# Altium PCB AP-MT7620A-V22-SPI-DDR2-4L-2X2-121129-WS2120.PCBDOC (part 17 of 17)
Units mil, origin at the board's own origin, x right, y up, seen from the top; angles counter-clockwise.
Board outline 7316 x 4279 mil, 4 copper layers (Top, Inner Layer 2, Inner Layer 3, Bottom), stack 35.4 mil thick; 640 components, 473 nets, 2041 pads, 2358 vias.
Unrouted connection lines stored in the file: 11.
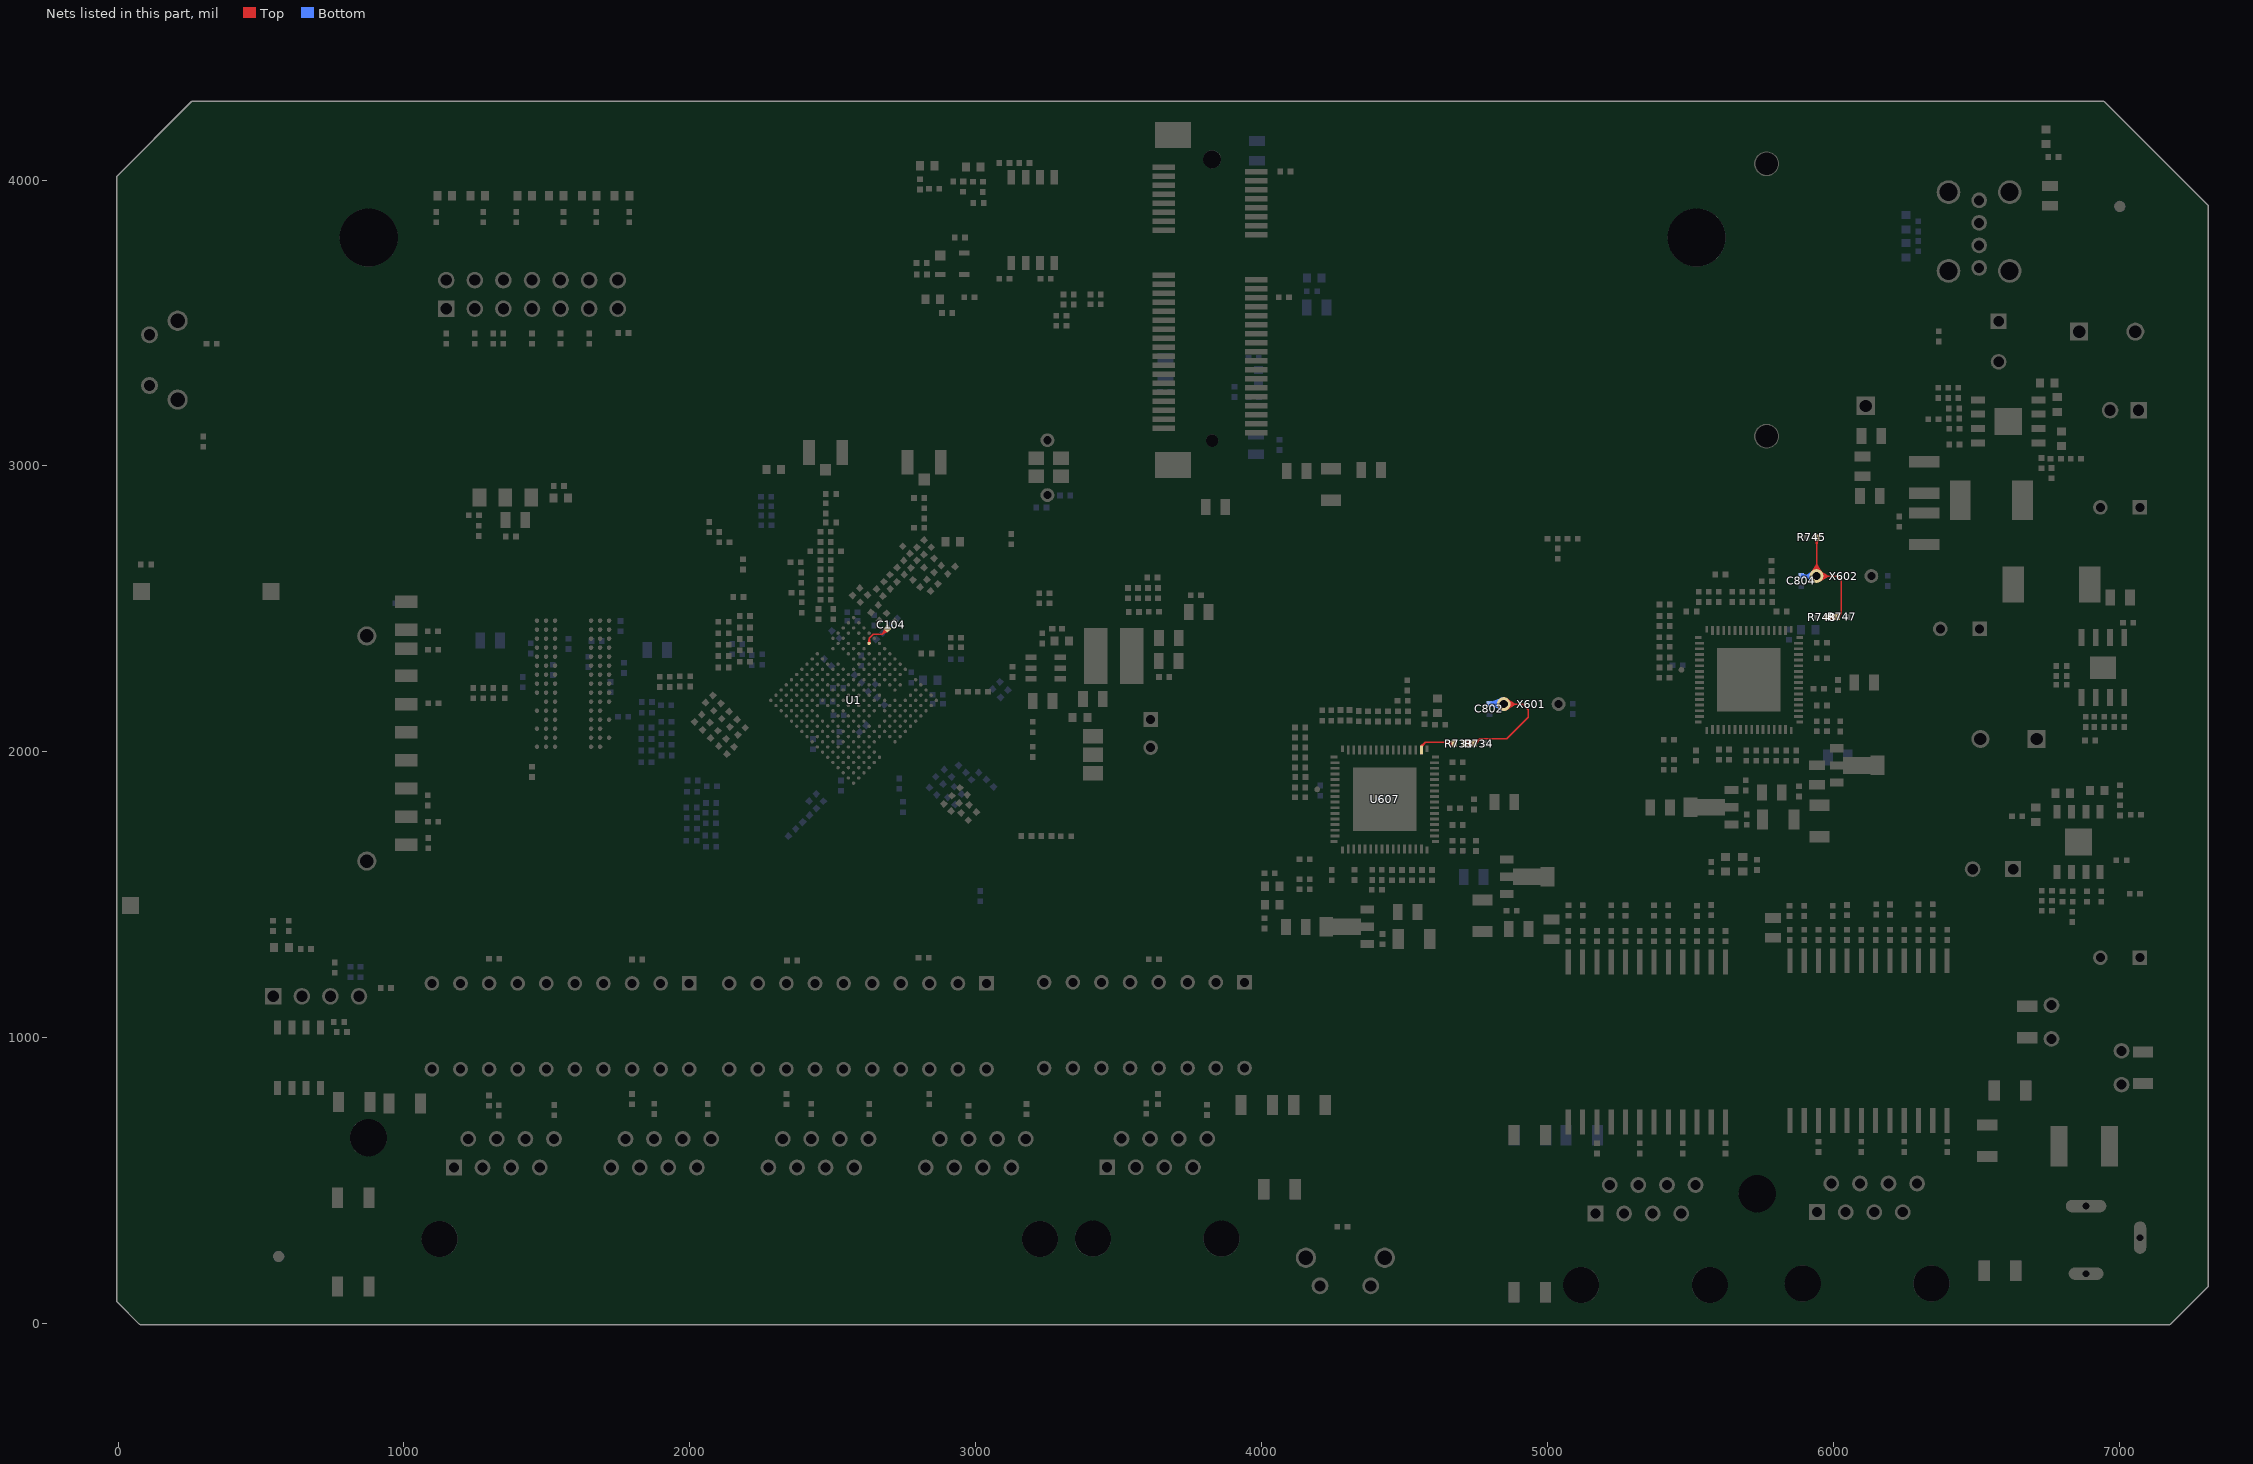
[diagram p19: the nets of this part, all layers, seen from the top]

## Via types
v1: diameter 20, hole 12, Top to Bottom, 2117 vias
v2: diameter 16, hole 8, Top to Bottom, 241 vias

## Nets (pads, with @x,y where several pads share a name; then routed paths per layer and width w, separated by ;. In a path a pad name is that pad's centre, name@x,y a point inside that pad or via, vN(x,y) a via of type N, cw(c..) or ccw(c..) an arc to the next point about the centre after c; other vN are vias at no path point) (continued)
X2_IP1001-21_1-CPU-RT0: C804.1 R745.1 R747.1 R748.1 X602.2 | length 2038.9
  Top w5: X602.2@5920.23,2621.62 5942,2654.28 ; X602.2@5924.7,2619.05 5942,2654.28 ; X602.2@5929.4,2617.11 5942,2654.28 ; X602.2@5934.26,2615.81 5942,2654.28 ; R745.1@5934.58,2748.88 5942,2725 ; X602.2@5941.5,2608.36 5980.14,2615.05 ; X602.2@5941.5,2621.74 5980.14,2615.05 ; X602.2@5942.68,2603.47 5980.14,2615.05 ; X602.2@5942.68,2626.63 5980.14,2615.05 ; X602.2@5944.49,2598.72 5980.14,2615.05 ; X602.2@5944.49,2631.38 5980.14,2615.05 ; X602.2@5946.94,2594.19 5980.14,2615.05 ; X602.2@5946.94,2635.91 5980.14,2615.05 ; X602.2@5947.63,2615.44 5942,2654.28 ; R745.1@5949.42,2748.88 5942,2725 ; X602.2@5952.55,2616.48 5942,2654.28 ; X602.2@5957.35,2618.16 5942,2654.28 ; X602.2@5961.95,2620.48 5942,2654.28 ; R748.1@5979.01,2470.95 6012.95,2470.95 R747.1@6014,2472 ; R748.1@5980.14,2463.53 6004.01,2470.95 R748.1@5980.14,2478.37 ; R747.1@6009.8,2478.21 6028,2486 ; R747.1@6011.29,2478.99 R748.1@5988.3,2466.07 ; R747.1@6011.83,2464.82 R748.1@5986.89,2476.27 ; R747.1@6012.57,2479.36 R748.1@5988.97,2470.95 ; R747.1@6013.19,2464.54 R748.1@5988.97,2470.95 ; R747.1@6014.14,2479.5 R748.1@5986.89,2476.27 ; R747.1@6014.63,2464.53 R748.1@5988.3,2466.07 ; R747.1@6020.21,2467.8 6028,2486 ; X602.2@5940.93,2615.05 6012.95,2615.05 6028,2600 6028,2486 ; X602.2@5940.93,2615.05 5942,2616.12 R745.1@5942,2750 5942,2725 ; X602.2@5940.93,2615.05 5942,2654.28 ; R748.1@5986.89,2476.27 R747.1@6014,2472 ; R748.1@5988.3,2466.07 R747.1@6014,2472 ; R748.1@5988.97,2470.95 R747.1@6014,2472 ; R747.1@6014,2472 6021.25,2472 6021.25,2479.25 6028,2486 ; R747.1@6014,2472 6028,2486
  Bottom w4.5: C804.1@5888.09,2612.75 5911.53,2615.05 ; C804.1@5888.35,2619.23 5911.53,2615.05 ; C804.1@5888.97,2608.31 5911.53,2615.05 ; C804.1@5889.58,2623.59 5911.53,2615.05 ; X602.2@5934.53,2594.04 5903.21,2615.05 ; X602.2@5934.53,2636.06 5903.21,2615.05 ; X602.2@5936.88,2598.06 5903.21,2615.05 ; X602.2@5936.88,2632.04 5903.21,2615.05 ; X602.2@5938.7,2602.28 5903.21,2615.05 ; X602.2@5938.7,2627.82 5903.21,2615.05 ; X602.2@5939.98,2606.64 5903.21,2615.05 ; X602.2@5939.98,2623.46 5903.21,2615.05 ; X602.2@5940.72,2611.09 5903.21,2615.05 ; X602.2@5940.72,2619.01 5903.21,2615.05 ; X602.2@5940.93,2615.05 5888.05,2615.05 5888,2615 C804.1@5888,2616 5911.53,2615.05
X2_IP1001-O_1-CPU-RT0: C802.1 R733.2 R734.1 X601.2 | length 2750.7
  Top w4.5: R734.1@4744,2029 R734.1@4745,2029
  Top w5: R733.2@4709.58,2021.51 R734.1@4735.68,2023.82 ; R733.2@4709.58,2036.49 R734.1@4735.68,2034.18 ; R733.2@4712.52,2021.94 R734.1@4735.68,2034.18 ; R733.2@4712.52,2036.06 R734.1@4735.68,2023.82 ; R734.1@4739.7,2035.15 4762.5,2046.5 ; R734.1@4742.88,2021.58 R733.2@4719,2029 ; R734.1@4742.88,2036.42 R733.2@4719,2029 ; R734.1@4749.9,2024.37 4762.5,2046.5 ; X601.2@4846.93,2167.05 4912.99,2167.05 4932,2148.04 4932,2121 4857.5,2046.5 4762.5,2046.5 ; X601.2@4847.5,2160.36 4886.14,2167.05 ; X601.2@4847.5,2173.74 4886.14,2167.05 ; X601.2@4848.68,2155.47 4886.14,2167.05 ; X601.2@4848.68,2178.63 4886.14,2167.05 ; X601.2@4850.49,2150.72 4886.14,2167.05 ; X601.2@4850.49,2183.38 4886.14,2167.05 ; X601.2@4852.94,2146.19 4886.14,2167.05 ; X601.2@4852.94,2187.91 4886.14,2167.05 ; R733.2@4710,2029 4745,2029 4762.5,2046.5 ; R733.2@4710,2029 R734.1@4735.68,2034.18 ; R733.2@4710,2029 R734.1@4735,2029 ; R733.2@4710,2029 R734.1@4735.68,2023.82 ; R733.2@4719,2029 R734.1@4744,2029 4762.5,2046.5 ; R734.1@4735,2029 4711.12,2036.42 R734.1@4735,2029 ; R734.1@4735,2029 4711.12,2021.58 R734.1@4735,2029
  Bottom w5: C802.1@4797.83,2160.55 4822.03,2167 ; C802.1@4798.42,2175.36 4822.03,2167 ; X601.2@4838.49,2147.05 C802.1@4803.88,2173.43 ; X601.2@4839.12,2187.31 C802.1@4804.42,2162.3 ; X601.2@4840.84,2146.21 C802.1@4806.19,2167.63 ; X601.2@4840.89,2187.91 4807.71,2167 ; X601.2@4840.94,2146.18 4807.71,2167 ; X601.2@4841.35,2151.3 C802.1@4803.88,2173.43 ; X601.2@4841.44,2188.06 C802.1@4806.19,2167.63 ; X601.2@4841.86,2182.98 C802.1@4804.42,2162.3 ; X601.2@4843.27,2150.74 C802.1@4806.19,2167.63 ; X601.2@4843.34,2183.37 4807.71,2167 ; X601.2@4843.39,2150.72 4807.71,2167 ; X601.2@4843.67,2155.8 C802.1@4803.88,2173.43 ; X601.2@4843.73,2183.45 C802.1@4806.19,2167.63 ; X601.2@4843.78,2145.57 C802.1@4804.42,2162.3 ; X601.2@4844.05,2178.4 C802.1@4804.42,2162.3 ; X601.2@4844.65,2188.64 C802.1@4803.88,2173.43 ; X601.2@4845.08,2155.48 C802.1@4806.19,2167.63 ; X601.2@4845.16,2178.63 4807.71,2167 ; X601.2@4845.19,2155.47 4807.71,2167 ; X601.2@4845.41,2178.66 C802.1@4806.19,2167.63 ; X601.2@4845.43,2160.51 C802.1@4803.88,2173.43 ; X601.2@4845.5,2150.4 C802.1@4804.42,2162.3 ; X601.2@4845.66,2173.64 C802.1@4804.42,2162.3 ; X601.2@4846.16,2183.74 C802.1@4803.88,2173.43 ; X601.2@4846.28,2160.37 C802.1@4806.19,2167.63 ; X601.2@4846.36,2160.36 4807.71,2167 ; X601.2@4846.34,2173.74 4807.71,2167 ; X601.2@4846.47,2173.75 C802.1@4806.19,2167.63 ; X601.2@4846.62,2155.34 C802.1@4804.42,2162.3 ; X601.2@4847.07,2178.76 C802.1@4803.88,2173.43 ; X601.2@4847.15,2160.34 C802.1@4804.42,2162.3 ; X601.2@4847.4,2173.75 C802.1@4803.88,2173.43 ; C802.1@4803.88,2173.43 X601.2@4846.93,2167.05 ; C802.1@4804.42,2162.3 X601.2@4846.93,2167.05 ; C802.1@4806.19,2167.63 X601.2@4846.93,2167.05 ; 4807.71,2167 X601.2@4846.93,2167.05 ; 4822.03,2167 C802.1@4797,2168 4797,2167 X601.2@4846.93,2167.05 X601.2@4846.93,2167.05
X2_IP1001_1-CPU-RT0: R733.1 U607.34 | length 327.5
  Top w4.5: U607.34@4557.05,2019.99 4572.7,2033.75 ; U607.34@4558.94,2007.28 4558.94,2020 4573,2034.06 4673,2034.06 4675,2032.06 4675,2029 R733.1@4674,2029 4649.41,2034.06 ; U607.34@4558.94,2018.11 4572.7,2033.75 ; U607.34@4561.06,2016.47 4572.7,2033.75 ; R733.1@4671.29,2021.74 4649.41,2034.06 ; R733.1@4673.14,2025.87 4649.41,2034.06 ; R733.1@4674.37,2036.74 4649.41,2034.06 ; R733.1@4674.45,2032.22 4649.41,2034.06
XTAL_V12A_1-CPU-RT0: C104.1 U1.B5 | length 270.6
  Top w4.5: U1.B5@2623.65,2379.42 2627.29,2397.19 ; U1.B5@2630.92,2379.42 2627.29,2397.19 ; C104.1@2684.71,2435.39 2675.63,2413.63 ; C104.1@2688.7,2433.26 2675.63,2413.63 ; C104.1@2693.55,2428.95 2675.63,2413.63 ; C104.1@2696.15,2425.25 2675.63,2413.63 ; 2627.29,2397.19 U1.B5@2627.29,2379.05 2627.29,2397.19 ; 2627.29,2397.19 2637.55,2407.45 2637.55,2407.55 2641,2411 2673,2411 2692.27,2430.27 C104.1@2691.27,2431.27 2675.63,2413.63
pads on no net: FM1.1 FM2.1 FM5.1 FM6.1 J6.1 J6.3 J6.5 J6.6 J6.7 J6.8 J6.10 J6.12 J6.14 J6.16 J6.17 J6.19 J6.20 J6.28 J6.30 J6.32 J6.36 J6.38 J6.45 J6.55 J6.56 J13.12 J44.H1 J44.H2 O1.1 O2.1 O3.1 O4.1 U1.A3 U1.B15 U1.C1 U1.E5 U1.E6 U1.P8 U1.P11 U1.P12 U1.R9 U1.R11 U1.R12 U1.R13 U1.T8 U1.T9 U1.T12 U1.T13 U1.U8 U1.U9 U1.U12 U13.33 U13.34 U15.9 U15.10 U16.2 U16.6 U16.8 U16.9 U16.11 U16.15 U22.A2 U22.A8 U22.E2 U22.E8 U22.R3 U22.R7 U607.1 U607.2 U607.4 U607.5 U607.6 U607.37 U609.1 U609.2 U609.4 U609.5 U609.6 U609.37 U614.9 U614.10 U615.9 U615.10

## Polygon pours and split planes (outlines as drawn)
CHGND_GE_A on Top "Top-CHGND_GE_A" (solid, remove dead copper, pour order 1000): 4972.28,833.28 5032.76,893.76 6569.24,893.76 6583,880 6583,545 6548,510 6548,115 6478,45 4994.48,45 4972.28,67.2
GND on Top "Top-GND" (solid, remove dead copper, pour order 1001): 16,107 16,3993 258,4235 6918,4235 7285,3869 7285,155 7165,35 6657,35 6618,74 6618,500 6653,535 6653,900 6598.76,954.24 4992.44,954.24 4905.08,866.88 4905.08,80.64 4864.44,40 4135,40 4098,77 4098,505 4203,610 4203,875 4013,1065 953,1065 788,900 788,65 763,40 83,40
CHGND on Top "Top-CHGND" (solid, remove dead copper, pour order 1002): 858,860 858,55 873,40 4003,40 4028,65 4028,530 4133,635 4133,850 3973,1010 1008,1010
CHGND_GE_A on Inner Layer 3 "Inner Layer 3-CHGND_GE_A" (solid, remove dead copper, pour order 1003): 4972.28,833.28 5032.76,893.76 6569.24,893.76 6583,880 6583,545 6548,510 6548,115 6478,45 4994.48,45 4972.28,67.2
SOC_1.2VD on Inner Layer 3 "Inner Layer 3-SOC_1.2VD" (solid, remove dead copper, pour order 1004): 2554,2310 2628.2,2384.2 2632.1,2384.2 2650.8,2365.5 2650.8,2357.8 2613,2320 2613,2290 2673,2230 2703,2230 2748,2275 2880,2275 2885,2270 2885,2225 2915,2195 2985,2195 2994,2186 2994,2155 2986,2147 2837.28,2147 2797.13,2187.5 2720.5,2187.5 2590,2057 2544,2103 2484.98,2103 2477.34,2097.66 2464.5,2106.5 2464.5,2149.4 2464.55,2169.45 2448.5,2185.5 2461,2218.35 2494,2218.35 2543.83,2268.17 2543.83,2299.5
GND on Inner Layer 3 "Inner Layer 3-GND" (solid, remove dead copper, pour order 1005): 2510,2290 2520,2290 2630,2400 2635,2400 2665,2370 2665,2355 2625,2315 2625,2295 2680,2240 2700,2240 2745,2285 3020,2285 3260,2525 3745,2525 3765,2545 3765,3145 3660,3250 3660,3960 3640,3980 2090,3980 2090,2710
1.8VD on Inner Layer 3 "Inner Layer 3-1.8VD" (solid, remove dead copper, pour order 1006): 1195,2747 1297,2849 1598,2849 1742,2705 2080,2705 2505,2280 2540,2280 2544,2276 2544,2265 2538,2259 2529,2259 2496,2226 2461,2226 2444,2193.5 2444,2183 2460,2167 2460,2092 2295,1927 2295,1840.46 2078.86,1623 1640,1623 1195,2068
3.3VD on Inner Layer 3 "Inner Layer 3-3.3VD" (solid, remove dead copper, pour order 1007): 2080,3990 3645,3990 3670,3965 3670,3255 3775,3150 3775,2540 3750,2515 3265,2515 3025,2275 2895,2275 2895,2230 2920,2205 2990,2205 3005,2190 3005,2150 2990,2135 2835,2135 2795,2175 2720,2175 2590,2045 2585,2045 2540,2090 2470,2090 2305,1925 2305,1835 2080,1610 1635,1610 1185,2060 1185,2750 1295,2860 1600,2860 1745,2715 2080,2715 2080,4235 258,4235 16,3994 16,107 83,40 763,40 788,65 788,900 953,1065 4013,1065 4203,875 4203,610 4098,505 4098,77 4135,40 4864.83,40 4905.08,80.03 4905.08,867 4992.57,954.24 6598.75,954.24 6653,900 6653,535 6618,500 6618,74 6657,35 7165,35 7285,155 7285,3869 6917.45,4235 2080,4235
CHGND on Inner Layer 3 "Inner Layer 3-CHGND" (solid, remove dead copper, pour order 1008): 858,860 858,55 873,40 4003,40 4028,65 4028,530 4133,635 4133,850 3973,1010 1008,1010
GND on Bottom "Bottom-GND" (solid, remove dead copper, pour order 1009): 16,107 16,3993 258,4235 6918,4235 7285,3869 7285,155 7165,35 6657,35 6618,74 6618,500 6653,535 6653,900 6598.76,954.24 4992.44,954.24 4905.08,866.88 4905.08,80.64 4869.44,45 4130,45 4098,77 4098,505 4203,610 4203,875 4013,1065 953,1065 788,900 788,65 763,40 83,40
CHGND_GE_A on Bottom "Bottom-CHGND_GE_A" (solid, remove dead copper, pour order 1010): 4972.28,833.28 5032.76,893.76 6569.24,893.76 6583,880 6583,545 6548,510 6548,115 6478,45 4994.48,45 4972.28,67.2
CHGND on Bottom "Bottom-CHGND" (solid, remove dead copper, pour order 1011): 858,860 858,55 873,40 4003,40 4028,65 4028,530 4133,635 4133,850 3973,1010 1008,1010
GND on Inner Layer 2 (split plane): 6948.8,4273.83 7310.83,3911.89 7312,3909.06 7312,132 7310.83,129.17 7310.82,129.16 7178.84,-2.82 7178.83,-2.83 7176,-4 78,-4 75.17,-2.83 75.16,-2.82 -2.82,75.16 -2.83,75.17 -4,78 -4,4011.84 -2.83,4014.66 255.94,4273.83 258.77,4275 6945.97,4275
GND on Inner Layer 2 (split plane): 7282.45,3867.94 7282.45,156.06 7163.94,37.55 6658.06,37.55 6620.55,75.06 6620.55,498.94 6654.8,533.2 6655.35,534.02 6655.55,535 6655.55,900 6655.35,900.98 6654.8,901.8 6600.56,956.04 6599.74,956.59 6598.76,956.79 4992.44,956.79 4991.46,956.59 4990.64,956.04 4903.28,868.68 4902.73,867.86 4902.53,866.88 4902.53,81.7 4868.38,47.55 4131.06,47.55 4100.55,78.06 4100.55,503.94 4204.8,608.2 4205.35,609.02 4205.55,610 4205.55,875 4205.35,875.98 4204.8,876.8 4014.8,1066.8 4013.98,1067.35 4013,1067.55 953,1067.55 952.02,1067.35 951.2,1066.8 786.2,901.8 785.65,900.98 785.45,900 785.45,66.06 761.94,42.55 84.06,42.55 18.55,108.06 18.55,3991.94 259.06,4232.45 6916.95,4232.45
CHGND on Inner Layer 2 (split plane): 4130.45,848.94 4130.45,636.06 4026.2,531.8 4025.65,530.98 4025.45,530 4025.45,66.06 4001.94,42.55 874.06,42.55 860.55,56.06 860.55,858.94 1009.06,1007.45 3971.94,1007.45
CHGND_GE_A on Inner Layer 2 (split plane): 6580.45,878.94 6580.45,546.06 6546.2,511.8 6545.65,510.98 6545.45,510 6545.45,116.06 6476.94,47.55 4995.54,47.55 4974.83,68.26 4974.83,832.22 5033.82,891.21 6568.18,891.21

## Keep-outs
Keep-Out Layer:
  pour cut-out: 6728,975 6728,755 6678,705 6678,235 6738,175 6738,30 7168,30 7168,975 6728,975
  pour cut-out: 983,700 983,905 1053,975 3978,975 4028,925 4028,840 4008,820 4008,670 3793,455 1118,455 1078,495 1078,605 983,700
  lines w8: 0,78 0,4011.84 258.77,4271 6945.97,4271 7308,3909.06 7308,132 7176,0 78,0 0,78

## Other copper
Top:
  region net 5V: 6934,3162 6934,3540 6733,3540 6733,3655 7074,3655 7103,3626 7103,3290 7013,3290 7013,3162 6934,3162
  pour cut-out: 1610,2470 1615,2470 1615,2455 1610,2455 1610,2470
  pour cut-out: 2268,2237 2268,2224 2270,2224 2270,2237 2268,2237
  pour cut-out: 4574,2038 4572,2036 4563,2045 4565,2047 4574,2038
  region net 3.3VD: 6478,1735 6478,2145 6598,2145 6598,1800 6663,1735 6663,1680 6533,1680 6478,1735
  region net 5VA: 6145,2950 6479,2950 6479,2811 6145,2811 6145,2950
  pour cut-out: 2630,1690 2652,1690 2652,1688 2630,1688 2630,1690
  pour cut-out: 2345,2393 2348,2393 2348,2380 2345,2380 2345,2393
  pour cut-out: 2916,2064 2919,2064 2919,2054 2916,2054 2916,2064
  region net CRTL12V_IP1001-2_1-CPU-RT0: 5835,2397 5835,2153 5828,2153 5828,2390 5835,2397
  region net 3.3VD: 3941,3118 3951,3128 4075,3128 4085,3118 4085,3086 4075,3076 3951,3076 3941,3086 3941,3118
  pour cut-out: 4832,1858 4832,1873 4828,1873 4828,1858 4832,1858
  region net P_DVDD_IP1001-2: 5592.99,2098.05 5565,2126.04 5565,2368.56 5594.74,2398.3 5758.99,2398.3 5758.99,2384.05 5749.99,2375.05 5590.99,2375.05 5586.5,2370.56 5586.5,2123.54 5600.99,2109.05 5600.99,2098.05 5592.99,2098.05
  region net D1_1-CPU-RT0: 3276,2350 3460,2350 3460,2235 3276,2235 3276,2268 3333,2268 3333,2315 3276,2315 3276,2350
  region net 12V: 6864,1878 6910,1878 6910,1760 6864,1760 6864,1878
  region net SW2_5-POWER0: 6687,3206 6888,3206 6888,3163 6687,3163 6687,3206
  region net 3.3VD: 4568,1381 4655,1381 4655,1309 4568,1309 4568,1381
  region net 3.3VD: 5915,1748.1 5920,1753.1 5982,1753.1 5987,1748.1 5987,1689 5982,1684 5920,1684 5915,1689 5915,1748.1
  pour cut-out: 1050,2405 1035,2405 1035,2385 1050,2385 1050,2405
  region net P_VDDO_IP1001-2: 5618,1878 5724,1878 5736,1890 5765,1890 5772,1883 5772,1726 5770,1724 5731,1724 5727,1728 5727,1835 5713,1849 5619,1849 5615,1853 5615,1875 5618,1878
  pour cut-out: 6413,3015 6693,3015 6693,2745 6413,2745 6413,3015
  region net SOC_1.2VD: 2710,2200 2738,2228 2754,2228 2761,2235 2761,2256 2759,2258 2725,2258 2685,2218 2685,2212 2697,2200 2710,2200
  region net 3.3VD: 5528.99,2008.05 5528.99,2106.05 5518.99,2106.05 5518.99,2008.05 5528.99,2008.05
  region net 5VD_E: 5430,2958 6125,2958 6125,2836 5430,2836 5430,2958
  region net SOC_1.5VD: 3375,2141 3370,2136 3370,2030 3375,2025 3445,2025 3450,2030 3450,2090 3587.5,2227.5 3635,2227.5 3658.75,2251.25 3658.75,2415 3686.88,2443.12 3752,2443.12 3765.94,2457.06 3765.94,2579.06 3720,2625 3670,2625 3660,2615 3660,2561.23 3650,2551.23 3628,2551.23 3623.38,2546.62 3623.38,2473 3584.69,2434.31 3584.69,2433 3506,2433 3506,2235 3488,2217 3429,2217 3411,2199 3411,2162 3390,2141 3375,2141
  region net P_AVDDH_IP1001: 4737.99,1463.05 4867.99,1463.05 4867.99,1513.05 4737.99,1513.05 4737.99,1463.05
  region net 5V: 6218,3460 6793,3460 6793,3655 6733,3655 6653,3575 6108,3575 6038,3505 6038,3020 6133,3020 6133,3145 6163,3175 6163,3405 6218,3460
  region net 3.3VD: 5828,1798 5882,1798 5882,1690 5828,1690 5828,1798
  region net 5VD_E: 6045,2981 6126,2981 6126,2847 6045,2847 6045,2981
  region net 12V: 6687,3144 7051,3144 7051,3105 6687,3105 6687,3144
  region net 12V: 6864,1974 6908,1974 6908,1858 6864,1858 6864,1974
  region net 5VD_0: 6718,4140 6763,4140 6763,4060 6783,4040 6783,3965 6718,3965 6718,4140
  pour cut-out: 6788,3650 7077,3650 7098,3629 7098,3145 6788,3145 6788,3650
  region net 5VD_E: 3698,3195 3698,3165 3837,3165 3837,3195 3698,3195
  pour cut-out: 3142,1756 3127,1741 3125,1743 3140,1758 3142,1756
  region net P_AVDD_IP1001-2: 5988,1980 6043,1980 6073,2010 6168,2010 6188,1990 6188,1900 6183,1895 6163,1895 6133,1925 5988,1925 5988,1980
  region net 12V: 6638,1075 7113,1075 7133,1095 7133,3230 7033,3230 7033,2710 6953,2630 6953,2370 6993,2370 6993,2570 7028,2605 7053,2605 7078,2580 7078,1470 7003,1395 7003,1190 6988,1175 6658,1175 6638,1155 6638,1075
  region net 12V_L_5-POWER0: 6953,445 6953,315 6763,315 6728,350 6728,895 6638,985 6638,1020 6823,1020 6823,575 6953,445
  region net 5VA: 6453,2300 6453,2480 6388,2545 6388,2950 6488,2950 6488,2580 6598,2470 6598,2360 6538,2300 6453,2300
  region net 3.3VD: 3935,4085 3940,4090 4070,4090 4075,4085 4075,4025 4070,4020 3940,4020 3935,4025 3935,4085
  pour cut-out: 4166,1776 4166,1757 4170,1757 4170,1776 4166,1776
  region net P_DVDD_IP1001: 4431.99,1359.05 4344.99,1359.05 4302.99,1317.05 4135.99,1317.05 4135.99,1463.05 4300.99,1463.05 4341.99,1422.05 4382.99,1422.05 4431.99,1373.05 4431.99,1359.05
  pour cut-out: 4205,1837 4205,1828 4208,1828 4208,1837 4205,1837
  region net SOC_1.2VD: 2856,2182 2856,2170 2946,2170 2946,2182 2856,2182
  region net GND_L_5-POWER0: 6773,200 6793,220 6988,220 7043,275 7043,470 6937,576 6937,814 6988,865 7123,865 7123,105 7078,60 6793,60 6773,80 6773,200
  region net P_VDDO_IP1001: 4461,1306 4499,1306 4506,1313 4506,1474 4498,1482 4467,1482 4436,1513 4436,1564 4433,1567 4410,1567 4407,1564 4407,1503 4369,1465 4347,1465 4342,1460 4342,1437 4347,1432 4450,1432 4458,1424 4458,1309 4461,1306
  region net 3.3VD: 4738,1391 4811,1391 4811,1311 4738,1311 4738,1391
  region net SOC_1.2VD: 3185,2085 3180,2080 3180,2013 3190.5,2002.5 3210,2002.5 3243.75,1968.75 3243.75,1950 3256.88,1936.88 3335,1936.88 3361.56,1963.44 3483.44,1963.44 3591.72,2071.72 3645,2071.72 3656.64,2083.36 3656.64,2155 3640.82,2170.82 3584.82,2170.82 3470,2056 3470,2030 3456.46,2016.46 3360,2016.46 3355.73,2020.73 3355.73,2135 3350.36,2140.36 3320,2140.36 3264.82,2085 3185,2085
  region net 1.8VD: 2483,2231 2495,2231 2535,2271 2535,2275 2521,2275 2483,2237 2483,2231
  region net SW1_5-POWER0: 6808,1923 6852,1923 6852,1760 6808,1760 6808,1923
  pour cut-out: 2673,1655 2673,1658 2690,1658 2690,1655 2673,1655
  region net 3.3VD: 3618,3320 3628,3330 3743,3330 3753,3320 3753,3285 3743,3275 3628,3275 3618,3285 3618,3320
  pour cut-out: 973,1303 975,1303 975,1289 973,1289 973,1303
  region net P_AVDD_IP1001: 4803.99,1534.05 4892.95,1534.05 4957.95,1469.05 5030,1469.05 5030,1657.05 4944.05,1657.05 4875,1588 4803.99,1588 4803.99,1534.05
  region net SOC_1.2VD: 2607,2067 2613,2067 2626,2054 2631,2059 2631,2065 2629,2067 2629,2086 2633,2090 2633,2110 2637,2118 2604,2085 2604,2070 2607,2067
  region net 5VD_E_A: 4138,2950 4367,2950 4367,3196 4279,3284 4138,3284 4138,2950
  pour cut-out: 5955,2314 5958,2314 5958,2306 5955,2306 5955,2314
  region net 3.3VD: 6558,1431 6558,1725 6663,1725 6663,1473 6621,1431 6558,1431
  region net P_DVDD_IP1001: 4318.99,1680.05 4299.49,1699.55 4299.49,1959.05 4320.74,1980.3 4484.99,1980.3 4484.99,1966.05 4475.99,1957.05 4316.99,1957.05 4308.99,1949.05 4308.99,1709.05 4326.99,1691.05 4326.99,1680.05 4318.99,1680.05
  region net 12V: 6864,1994 7107,1994 7107,1949 6864,1949 6864,1994
  region net 5VD_E_A: 4033.08,3275 4033.08,3175 4158,3175 4158,3275 4033.08,3275
  region net 1.8VD: 1281,3187 1281,3082 1321,3042 1321,2859.5 1302.5,2841 1302.5,2729.5 1312.5,2719.5 1359,2719.5 1373.5,2734 1373.5,2840.5 1390.5,2857.5 1390.5,3039.5 1435,3084 1435,3185.5 1428,3192.5 1286.5,3192.5 1281,3187
  pour cut-out: 5534,2067 5547,2067 5547,2062 5534,2062 5534,2067
  pour cut-out: 2990,2189 2990,2176 2996,2176 2996,2189 2990,2189
  pour cut-out: 6443,2150 6803,2150 6803,1820 6443,1820 6443,2150
  region net P_DVDD_IP1001-2: 5705.99,1777.05 5618.99,1777.05 5576.99,1735.05 5409.99,1735.05 5409.99,1881.05 5574.99,1881.05 5615.99,1840.05 5656.99,1840.05 5705.99,1791.05 5705.99,1777.05
  region net SW11_5-POWER0: 6627,2889 6627,2761 6643,2745 6703,2745 6703,2889 6627,2889
  region net SW11_5-POWER0: 6623,2950 6623,2730 6893,2460 6893,2370 6938,2370 6938,2655 6703,2890 6703,2950 6623,2950
  pour cut-out: 2599,1725 2599,1723 2620,1723 2620,1725 2599,1725
  region net SW2_5-POWER0: 6823,3165 6823,3505 6908,3505 6908,3165 6823,3165
  region net P_AVDDH_IP1001-2: 5874.8,1907.7 6038.6,1907.7 6045,1901.3 6045,1883 5989.8,1827.8 5989.8,1793 5986.2,1789.4 5914.8,1789.4 5914.8,1849.7 5896.5,1868 5866.95,1868 5863,1871.91 5863,1895.9 5874.8,1907.7
  pour cut-out: 6129,2838 6140,2838 6140,2834 6129,2834 6129,2838
  region net GND: 6933,1025 6918,1010 6918,945 6933,930 7113,930 7128,945 7128,1010 7113,1025 6933,1025
  region net 5VD_E: 5938,2924 6125,2924 6125,2837 5938,2837 5938,2924
  region net 12V: 6900,1879 6983,1962 6983,1993 6878,1993 6878,1879 6900,1879
  region net SW1_5-POWER0: 6643,2145 6818,2145 6853,2110 6853,1890 6643,1890 6643,2145
  pour cut-out: 5380,2426 5384,2426 5384,2418 5380,2418 5380,2426
  region net 3.3VD: 1418,2857 1534,2857 1544,2867 1544,2941 1534,2951 1423,2951 1414,2942 1414,2861 1418,2857
  pour cut-out: 4261,1644 4273,1644 4273,1649 4261,1649 4261,1644
  pour cut-out: 4254,2225 4259,2225 4259,2215 4254,2215 4254,2225
  region net CRTL12V_IP1001_1-CPU-RT0: 4560,1981 4560,1731 4553,1731 4553,1974 4560,1981
  text "L1 COMPONENT SIDE" at 1197,-1049 h50
Inner Layer 3:
  pour cut-out: 6481.5,2078.5 6547,2078.5 6547,2013 6481.5,2013 6481.5,2078.5
  region net GND: 2557.07,2257.93 2542.93,2257.93 2492.07,2207.07 2492.07,2192.93 2580.43,2104.57 2594.57,2104.57 2645.43,2155.43 2645.43,2169.57 2557.07,2257.93
  text "L3 INNER LAYER 3" at 1197,-1049 h50
Bottom:
  pour cut-out: 3096,1664 3099,1664 3099,1649 3096,1649 3096,1664
  pour cut-out: 4340,2472 4340,2457 4344,2457 4344,2472 4340,2472
  pour cut-out: 2729,1951 2742,1951 2742,1953 2729,1953 2729,1951
  pour cut-out: 2295,2334.5 2315,2334.5 2315,2300 2295,2300 2295,2334.5
  region net 3.3VD: 1418,2857 1534,2857 1544,2867 1544,2941 1534,2951 1423,2951 1414,2942 1414,2861 1418,2857
  pour cut-out: 3639,1661 3641,1661 3641,1650 3639,1650 3639,1661
  region net 3.3VD: 3941,3118 3951,3128 4075,3128 4085,3118 4085,3086 4075,3076 3951,3076 3941,3086 3941,3118
  pour cut-out: 3702,2051 3709,2051 3709,2048.5 3702,2048.5 3702,2051
  pour cut-out: 5658,2592 5658,2586 5670,2586 5670,2592 5658,2592
  pour cut-out: 2824,2001 2838,2001 2838,2004 2824,2004 2824,2001
  region net SOC_1.5VD: 3657,2627 3670,2640 3715,2640 3725,2630 3725,2565 3715,2555 3670,2555 3657,2568 3657,2627
  pour cut-out: 4559,1635 4567,1635 4567,1632 4559,1632 4559,1635
  pour cut-out: 3092,1786 3078,1772 3081,1769 3095,1783 3092,1786
  region net P_VDDO_IP1001: 4397,1489 4402,1494 4441,1494 4446,1489 4446,1475 4441,1470 4402,1470 4397,1475 4397,1489
  pour cut-out: 2409,2058 2418,2058 2418,2056 2409,2056 2409,2058
  pour cut-out: 5214,2382 5214,2364 5220,2364 5220,2382 5214,2382
  region net 3.3VD: 3933,4089 3943,4099 4067,4099 4077,4089 4077,4028 4067,4018 3943,4018 3933,4028 3933,4089
  region net P_AVDD_IP1001: 4763.99,1536.05 4829.99,1536.05 4829.99,1592.05 4763.99,1592.05 4763.99,1536.05
  pour cut-out: 5577,2590 5577,2582 5585,2582 5585,2590 5577,2590
  region net 3.3VD: 3638,3320 3653,3335 3738,3335 3753,3320 3753,3260 3743,3250 3678,3250 3663,3265 3663,3275 3638,3300 3638,3320
  region net P_AVDD_IP1001-2: 6037.99,1954.05 6103.99,1954.05 6103.99,2010.05 6037.99,2010.05 6037.99,1954.05
  pour cut-out: 3648,1782 3650,1782 3650,1767 3648,1767 3648,1782
  text "L4 SOLDER SIDE" at 1197,-1049 h50
Inner Layer 2 (plane layer: these items are gaps in the copper):
  lines w5: 16,107 16,3993 258,4235 6918,4235 7285,3869 7285,155 7165,35 6657,35 6618,74 6618,500 6653,535 6653,900 6598.76,954.24 4992.44,954.24 4905.08,866.88 4905.08,80.64 4869.44,45 4130,45 4098,77 4098,505 4203,610 4203,875 4013,1065 953,1065 788,900 788,65 763,40 83,40 16,107 ; 858,55 858,860 1008,1010 3973,1010 4133,850 4133,635 4028,530 4028,65 4003,40 873,40 858,55 ; 4972.28,67.2 4994.48,45 6478,45 6548,115 6548,510 6583,545 6583,880 6569.24,893.76 5032.76,893.76 4972.28,833.28 4972.28,67.2
  text "L2 INNER LAYER 2" at 1197,-1049 h50
Multi-Layer:
  lines w8: -25,0 30,0 ; 0,-30 0,34
  lines w10: 497,-1114 3222,-1114 ; 497,-922 3223,-922 ; 497,-722 3223,-722 ; 497,-522 3223,-522 ; 897,-1424 897,-1114 ; 897,-1254 3222,-1254 ; 1093,-1114 1093,-522 ; 1557,-1424 1557,-1114 ; 2107,-1424 2107,-1114 ; 2573,-924 2573,-292 ; 2767,-1424 2767,-1114 ; 3053,-922 3053,-722 ; 497,-1424 497,-292 3223,-292 3223,-1424 497,-1424
  text "TEL:(03)560-0868" at 1883,-382 h40
  text "Eng:" at 2603,-382 h40
  text "Moly" at 2774,-387 h50
  text "Media Tek Inc." at 563,-462 h70
  text "FAX:(03)560-0818" at 1873,-482 h40
  text "Ext:" at 2603,-482 h40
  text "31360" at 2768,-487 h50
  text "MODEL NAME" at 533,-652 h50
  text "Date:" at 2607,-654 h40
  text "2012/12/4" at 2824,-659 h40
  text "AP_MT7620A_V22" at 1160,-660 h50
  text "MODEL NO." at 543,-852 h50
  text "LAYERS" at 2643,-852 h40
  text "4" at 3113,-852 h50
  text "WS2120" at 1186,-857 h50
  text "LAYER" at 543,-1062 h50
  text "Through Hole Via" at 942,-1214 h40
  text "Plugging Resin" at 1602,-1214 h40
  text "Blind Via" at 2302,-1214 h40
  text "Buried Via" at 2832,-1214 h40
  text "Via Type:" at 537,-1294 h40
  text "Yes" at 1152,-1369 h40
  text "No" at 1772,-1369 h40
  text "No" at 2420,-1369.5 h40
  text "N0" at 2961,-1369.5 h40

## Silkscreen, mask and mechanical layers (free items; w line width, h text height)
Silkscreen Top:
  drawing of 272 lines, arcs and shapes, not listed
  text "+" at 2736,4052 h40
  text "+" at 2901,4047 h40
  text "LED2" at 1445,3995 h25 r90
  text "WLED" at 1755,3995 h25 r90
  text "LED4" at 1165,3990 h25 r90
  text "LED1" at 1275,3990 h25 r90
  text "WLAN _LED" at 1545,3990 h25 r90
  text "LED3" at 1645,3990 h25 r90
  text "+" at 1770,3980 h40
  text "+" at 1565,3975 h40
  text "+" at 1659,3975 h40
  text "+" at 1304,3963 h40
  text "+" at 1349,3963 h40
  text "+" at 1061,3961 h40
  text "USB 0" at 6688,3745 h30
  text "B" at 2514,3550 h25
  text "A" at 2118,3519 h25
  text "5V" at 5063,2855 h30
  text "A" at 2374,2835 h25
  text "K" at 5202,2783 h25
  text "B" at 2703,2775 h25
  text "GE 1" at 5653,2700 h30
  text "H" at 4561,2628 h25
  text "K" at 5655.5,2600 h25
  text "H" at 5403,2545 h25
  text "GE 0" at 4242,2237 h30
  text "+" at 5702,1643 h40
  text "+" at 5569,1641 h40
  text "C" at 4023,1600 h25
  text "+" at 4078.8,1569.5 h40
  text "10/100" at 3838,1520 h25
  text "E" at 5343,1495 h25 r90
  text "1000" at 5700,1465 h25 r90
  text "1000" at 3860,1440 h25
  text "+" at 4100,1435 h40
  text "F" at 5943,1430 h25
  text "10/100" at 5650,1420 h25 r90
  text "C" at 3708,1365 h25
  text "+" at 518,1241 h40
  text "E" at 4628,1130 h25 r90
  text "F" at 4798,605 h25
  text "WS2120" at 562,314.5 h50 r90
  text "12V" at 7135,160 h40
  text "AP_MT7620A_V22" at 447,109 h50 r90
  text "SILK SCREEN TOP" at 1197,-1049 h50
Silkscreen Bottom:
  circle w5: c3551,2057 r25.06
  circle w5: c2415,2211 r25.61
  lines w5: 1813,1940 1813,2225 2173,2225 2173,1940 1813,1940 ; 1863,1365 1863,1670 1963,1670 1963,1925 2123,1925 2123,1635 2068,1635 2068,1365 1863,1365 ; 2352,2097 2352,2249 2520,2249 2568,2297 2568,2373 2626,2373 2626,2328 2738,2216 2738,2152 2615,2029 2561,2029 2561,2097 2352,2097 ; 2778,2070 2863,2070 2863,2140 2913,2140 2913,2220 2823,2220 2823,2150 2778,2150 2778,2070 ; 3258.5,2049.5 3456,2247 3578,2125 3578,1980 3453,1855 3258.5,2049.5
  text "M" at 2404,2195 h25
  text "M" at 3540,2041 h25
  text "SILK SCREEN BOTTOM" at 2097,-1049 h50
Paste Mask Top:
  text "SMD PASTE Top" at 1197,-1049 h50
Paste Mask Bottom:
  text "SMD PASTE Bottom" at 2022,-1049 h50
Solder Mask Top:
  region: 4673,3213.5 5083,3213.5 5083,2985.5 4673,2985.5 4673,3213.5
  region: 4673,4167.5 5083,4167.5 5083,3941.5 4673,3941.5 4673,4167.5
  text "MASK Top" at 1197,-1049 h50
Solder Mask Bottom:
  text "MASK Bottom" at 1772,-1049 h50
Assembly Drawing Bottom:
  drawing of 784 lines, arcs and shapes, not listed
Layer_5:
  text "L5 INNER LAYER 5" at 1297,-1064 h50
Layer_6:
  text "SOLDER SIDE" at 1877,-1064 h50
Layer_18 and Layer_19 and Layer_20 and Layer_25:
  lines w10: 3219.99,-1422.46 4839.99,-1422.46 4839.99,-292.46 3224.99,-292.46 ; 3223.88,-1253.48 4839.06,-1253.48 ; 3224.07,-521.63 4836.54,-521.63 ; 3224.39,-921.57 4839.52,-921.57 ; 3224.45,-1113.32 4838.73,-1113.32 ; 3224.51,-721.36 4839.63,-721.36 ; 3499.99,-517.66 3499.99,-297.46 ; 4244.99,-1420.5 4244.99,-522.62 ; 4544.99,-1417.46 4544.99,-525.34 ; 5212.95,-1441.05 6842.95,-1441.05 ; 5212.95,-1331.05 6842.95,-1331.05 ; 5212.95,-1221.05 6842.95,-1221.05 ; 5212.95,-1111.05 6842.95,-1111.05 ; 5212.95,-1001.05 6842.95,-1001.05 ; 5212.95,-891.05 6842.95,-891.05 ; 5212.95,-781.05 6842.95,-781.05 ; 5212.95,-671.05 6842.95,-671.05 ; 6362.95,-1551.05 6362.95,-531.05 ; 7084.95,-1443.05 8714.95,-1443.05 ; 7084.95,-1333.05 8714.95,-1333.05 ; 7084.95,-1223.05 8714.95,-1223.05 ; 7084.95,-1113.05 8714.95,-1113.05 ; 7084.95,-1003.05 8714.95,-1003.05 ; 7084.95,-893.05 8714.95,-893.05 ; 7084.95,-783.05 8714.95,-783.05 ; 7084.95,-673.05 8714.95,-673.05 ; 8234.95,-1553.05 8234.95,-533.05 ; 8887.95,-1446.05 10517.95,-1446.05 ; 8887.95,-1336.05 10517.95,-1336.05 ; 8887.95,-1226.05 10517.95,-1226.05 ; 8887.95,-1116.05 10517.95,-1116.05 ; 8887.95,-1006.05 10517.95,-1006.05 ; 8887.95,-896.05 10517.95,-896.05 ; 8887.95,-786.05 10517.95,-786.05 ; 8887.95,-676.05 10517.95,-676.05 ; 10037.95,-1556.05 10037.95,-536.05 ; 5212.95,-1551.05 6842.95,-1551.05 6842.95,-531.05 5212.95,-531.05 5212.95,-1551.05 ; 7084.95,-1553.05 8714.95,-1553.05 8714.95,-533.05 7084.95,-533.05 7084.95,-1553.05 ; 8887.95,-1556.05 10517.95,-1556.05 10517.95,-536.05 8887.95,-536.05 8887.95,-1556.05
  text "RF/USB/PCIE/ETH_20/GE_HP" at 3535,-385 h25
  text "Class" at 3248.42,-455.76 h50
  text "PHY_IC/GE_PHY/DDR/GE_PHY/PHY_ETH" at 3540,-470 h25
  text "Update Footprint Table" at 5232.95,-481.05 h50
  text "Update Footprint Table" at 7104.95,-483.05 h50
  text "Update Footprint Table" at 8907.95,-486.05 h50
  text "Footprint Name" at 5502.95,-621.05 h40
  text "Update Date" at 6402.95,-621.05 h40
  text "Footprint Name" at 7374.95,-623.05 h40
  text "Update Date" at 8274.95,-623.05 h40
  text "Footprint Name" at 9177.95,-626.05 h40
  text "Update Date" at 10077.95,-626.05 h40
  text "Via" at 4634.99,-652.46 h50
  text "Component Ref" at 3455.47,-654.74 h50
  text "W/St" at 4294.99,-667.46 h50
  text "2012.11.29" at 10203,-743 h25
  text "SB/0402" at 9157,-747 h25
  text "C0402" at 5399.97,-754.69 h25
  text "SOP8/SMD/P1.27/IT7653" at 7271.97,-756.69 h25
  text "2012.12.04" at 6422.04,-762 h25
  text "2012.06.28" at 8294.04,-764 h25
  text "2012.12.04" at 10208,-853 h25
  text "CON10P/SMD/R/F/7SDCN-B0-1X14" at 9162,-854.5 h25
  text "R0402" at 5399.41,-856.34 h25
  text "SOIC8/SMD/P1.27/AT26DF321" at 7270.97,-855.69 h25
  text "2012.12.04" at 6432.54,-857 h25
  text "4/4" at 4316,-860 h50
  text "8/16" at 4605,-862 h50
  text "U1" at 3681,-863 h50
  text "2012.06.28" at 8297.04,-863 h25
  text "L0402" at 9163.47,-959.69 h25
  text "2012.11.29" at 6422.04,-966.82 h25
  text "2012.12.04" at 10185.54,-967 h25
  text "SB/1206" at 5398.95,-971.05 h25
  text "2012.06.28" at 8301.04,-971 h25
  text "SOIC8/SMD/P1.27/AT24C04B-08B" at 7276.97,-971.69 h25
  text "2012.06.28" at 8308.04,-1075 h25
  text "MINI-PCI-EXPRESS/52P/SMD/R/F/C1720007" at 5398.95,-1080.05 h25
  text "FD" at 9169.97,-1079.69 h25
  text "DIP7X2/P2.54" at 7274.97,-1080.69 h25
  text "2012.11.29" at 6434.04,-1081.82 h25
  text "2012.12.04" at 10192.04,-1087 h25
  text "DIP2/P2.54" at 7283,-1187 h25
  text "2012.06.28" at 8314.04,-1189.5 h25
  text "SB1206" at 5405.41,-1191.34 h25
  text "2012.06.21" at 6444.04,-1190.82 h25
  text "L/IND/DIP/D6H14" at 7267,-1293.5 h25
  text "2012.06.28" at 8309.04,-1293.5 h25
  text "RJ45/8P/DIP/R/8208C-B01" at 5410.41,-1296.34 h25
  text "2012.06.21" at 6449.04,-1300.82 h25
  text "RJ45/32P/DIP/R/N3642-001" at 5407.41,-1397.34 h25
  text "2012.06.28" at 6453.04,-1398.82 h25
  text "VARISTOR/SMD/TVM5B150L103RY" at 7272,-1401.5 h25
  text "2012.06.28" at 8316.04,-1402.5 h25
  text "2012.07.03" at 8324.04,-1505.5 h25
  text "RJ45/8P/DIP/R/N3612-002" at 5406.41,-1507.34 h25
  text "DIP4/P2.54" at 7282,-1510.5 h25
  text "2012.06.28" at 6454.04,-1516.82 h25
Drill Drawing:
  text "DRILL DRAWING" at 2291.21,-1065.27 h50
